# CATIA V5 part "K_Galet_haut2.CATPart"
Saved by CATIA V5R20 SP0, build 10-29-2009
Part number: Galet_haut
Bounding box of the stored display mesh (mm): x 0 to 17.955, y -11.571 to 11.571, z -11.571 to 11.571
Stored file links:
  G:\Khaled_CFAO_2011\SIL\SIL_GR2\zthiebault\Khaled\CAD_ThinkMOTION\K_Galet_haut2.CATPart
  G:\Khaled_CFAO_2011\SIL\SIL_GR2\zthiebault\CATIA_zthiebault\Galet_droit.CATPart
  F:\Projet Thinkmotion\Catia\FINAL\HabillageFinal.CATProduct
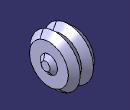
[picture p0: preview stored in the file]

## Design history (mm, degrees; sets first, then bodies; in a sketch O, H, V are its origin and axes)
Parameters
  LENGTH = 10.41 mm
  LENGTH = 9 mm
Set1
  Line1 "Droite_base_galetdroit": linked copy from another document
  Line2 "Droite_base_galetcontact2": linked copy from another document
Body1 (main body)
  Sketch1 on zx-plane, origin (0, 0, 0), H (-1, 0, 0), V (0, 0, 1)
    line L1 (0, 0) -> (-17.9551, 0)
    line L2 (-17.9551, 0) -> (-17.9551, -2)
    line L3 (-17.9551, -2) -> (-16.41, -3.9654)
    point P4 (-16.41, -3.9654)
    line L4 (-16.41, -3.9654) -> (-16.41, -8.9654)
    line L5 (-16.41, -8.9654) -> (-13.4742, -11.5712)
    line L6 (-13.4742, -11.5712) -> (-10.41, -9)
    point P7 (-10.41, -9)
    line L7 (-10.41, -9) -> (-7.3458, -11.5712)
    line L8 (-7.3458, -11.5712) -> (-4.41, -9)
    line L9 (-4.41, -9) -> (-4.41, -3)
    line L10 (-4.41, -3) -> (-1.3229, -3)
    line L11 (-1.3229, -3) -> (0, -1.5)
    line L12 (0, -1.5) -> (0, 0)
    construction line L13 (-13.4742, -11.5712) -> (-7.3458, -11.5712)
    axis line L14 (-4.41, -9) -> (-10.41, -9)
    reference projected line E1 (0, 0) -> (-10.41, 0) from Line1
    reference projected line E2 (-10.41, -9) -> (-10.41, 0) from Line2
    length L2 = 2
    length L4 = 5
    angle L6 L7 = 100
    length L6 = 4
    length L7 = 4 {= Sketch1.length(L6)}
    length L9 = 6
    length L11 = 2
    distance L1 P7 = 9 {= LENGTH}
    distance L4 P7 = 6
    length L12 = 1.5
    distance L12 P7 = 10.41 {= LENGTH}
    distance L9 P7 = 6 {= Sketch1.distance(L4 P7)}
    length L3 = 2.5
    horizontal: L1 H, L10 H, L13 H, L14 H
    vertical: L2 V, L4 V, L9 V, L12 V
    coincidence: L7 P4, E1 L1, P7 E2
  Shaft1: profile Sketch1, axis Sketch1.L1, angle 360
